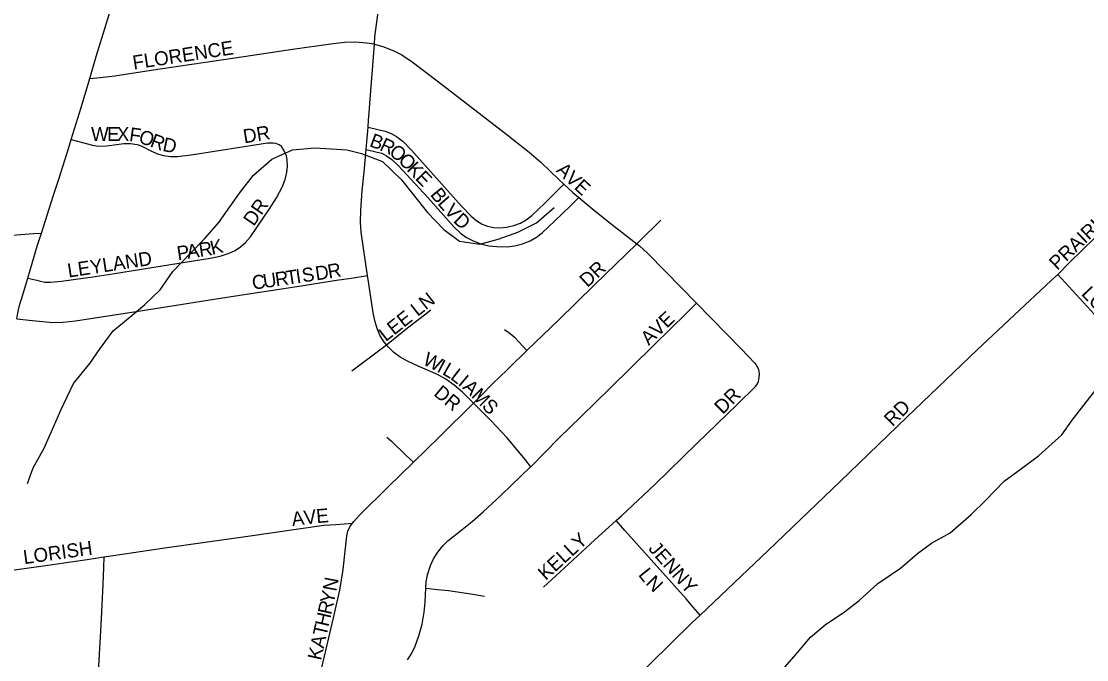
# Model space of a CAD drawing. Extents: x 1442749 to 1756758, y 235267 to 677782.
# Drawn here: x 1594493 to 1598304, y 531991 to 534274 of the extents above; entities that cross this region are included whole.
import ezdxf

# ---------------------------------------------------------------- set-up
doc = ezdxf.new("R2010")
doc.units = 0
for name, color, linetype in [('GM_X_City_Street', 7, 'Continuous'), ('GM_X_City_Street_Text', 7, 'Continuous'), ('GM_X_Minor_River', 7, 'Continuous'), ('GM_X_State_Route', 7, 'Continuous')]:
    doc.layers.add(name, color=color, linetype=linetype)

msp = doc.modelspace()

# ---------------------------------------------------------------- linework, layer by layer
at = {"layer": 'GM_X_City_Street'}
for points in [[(1595755.7, 534192.9), (1595757.6, 534218.5), (1595770, 534315.8), (1595780.6, 534376.9)], [(1594737.1, 534069.8), (1594774.5, 534073.6), (1594827, 534079), (1594956.8, 534099.6), (1595288, 534148.2), (1595463.2, 534174.5), (1595599.5, 534194.4), (1595648.1, 534199.8), (1595687, 534200.8), (1595729, 534197.9), (1595754.3, 534193.4), (1595755.7, 534192.9)], [(1595732.8, 533896.3), (1595734.8, 533921.3), (1595737.2, 533947.3), (1595740.8, 533996.3), (1595745.2, 534055.1), (1595755.7, 534192.9)], [(1595755.7, 534192.9), (1595785.3, 534184.1), (1595824.6, 534168.9), (1595853.2, 534154), (1595891.2, 534128.9), (1595985.4, 534058.1), (1596099.3, 533969.3), (1596224.2, 533873.2), (1596309.2, 533806.5), (1596351.4, 533770.3), (1596415, 533708.8), (1596433, 533692.4)], [(1595726.2, 533815.9), (1595726.3, 533816.6), (1595732.8, 533896.3)], [(1595732.8, 533896.3), (1595768.3, 533888), (1595793.9, 533882), (1595815.1, 533873.4), (1595835.1, 533862.1), (1595858.4, 533844), (1595888.4, 533813.8), (1595966.5, 533725), (1596067.8, 533613.2), (1596101.8, 533577.5), (1596122.1, 533560.9), (1596141.7, 533548.9), (1596160, 533541.9), (1596182.5, 533537.3), (1596205.4, 533535.9), (1596228.3, 533537.9), (1596253.9, 533543.7), (1596278.4, 533552.9), (1596298.6, 533563.9), (1596319.4, 533579.7), (1596364.4, 533622.9), (1596398.9, 533658), (1596433, 533692.4)], [(1594515.6, 533356.1), (1594547.6, 533348.2), (1594556.9, 533345.9), (1594576.9, 533341.8), (1594597, 533341.3), (1594636.6, 533344.9), (1594757, 533362.2), (1594818.6, 533371.8), (1595025.8, 533404.3), (1595168.4, 533426.8), (1595204.1, 533434.5), (1595235.7, 533444.9), (1595257.1, 533454.8), (1595276.9, 533467.8), (1595294.6, 533483.3), (1595312.2, 533503.7), (1595380.7, 533604.1), (1595405.9, 533642.8), (1595425.7, 533681.2), (1595436.6, 533709.2), (1595442.8, 533735.4), (1595444.5, 533755.7), (1595443.2, 533779.3), (1595440.6, 533793.3), (1595436.6, 533803.1), (1595431.8, 533813.2), (1595427.2, 533820.7), (1595421.6, 533828.9)], [(1594671, 533851.6), (1594706.2, 533842.2), (1594747.1, 533831.2), (1594769.1, 533828.4), (1594797.9, 533828.9), (1594859.8, 533837), (1594883.5, 533837), (1594907, 533833.3), (1594923.3, 533828.1), (1594956, 533811.5), (1594979.2, 533800.7), (1595000.6, 533794.3), (1595025.7, 533790.9), (1595051.3, 533791.4), (1595099.9, 533797.1), (1595372.8, 533839.4), (1595383.4, 533840.3), (1595393.2, 533840.3), (1595401.4, 533839), (1595407.9, 533836.8), (1595414.8, 533833.8), (1595421.6, 533828.9)], [(1595731.3, 533365.4), (1595708.6, 533520.5), (1595705.5, 533556), (1595706.6, 533598.2), (1595712.1, 533669.7), (1595719.5, 533734.9), (1595726.2, 533815.9)], [(1595726.2, 533815.9), (1595765.9, 533806.4), (1595781.8, 533802.6), (1595790.8, 533798.3), (1595799.4, 533793.8), (1595818, 533780.4), (1595841.5, 533757.7), (1595946.3, 533644.4), (1596040.1, 533539), (1596064.2, 533516.8), (1596085.4, 533501.4), (1596108.5, 533489), (1596136.1, 533478.6), (1596164.9, 533471.8), (1596194.2, 533468.6), (1596230.3, 533468.3), (1596256.3, 533471.6), (1596284.9, 533478.9), (1596312.5, 533489.5), (1596335.4, 533502.2), (1596356.3, 533518), (1596401.1, 533561.4), (1596455.4, 533613.8), (1596487.2, 533644.4)], [(1596433, 533692.4), (1596466, 533662.4), (1596487.2, 533644.4)], [(1596487.2, 533644.4), (1596543.8, 533596.5), (1596608.6, 533545.9), (1596694.2, 533478.5)], [(1596694.2, 533478.5), (1596705.5, 533489.5), (1596780.4, 533562.9)], [(1598200, 533369.2), (1598243.4, 533413.1), (1598332.2, 533499.3), (1598406.1, 533567.9)], [(1593624.3, 533445.5), (1593652.9, 533447.6), (1593778.5, 533456.7), (1593885.8, 533465.2), (1594098.2, 533482.8), (1594287.9, 533496.5), (1594421.9, 533507.3), (1594475.5, 533510.9), (1594536.2, 533515), (1594564.6, 533516.9)], [(1596300.8, 533096.9), (1596414.7, 533205.5), (1596542.8, 533332.3), (1596694.2, 533478.5)], [(1596694.2, 533478.5), (1596703.8, 533471), (1596733, 533445), (1596796.8, 533379.2), (1596908, 533266.1)], [(1594476.5, 533210.3), (1594520.7, 533206), (1594605.3, 533197.7), (1594640.9, 533198.6), (1594686.2, 533203.3), (1594926.3, 533240.4), (1595227.9, 533287.7), (1595477.7, 533326.3), (1595620.5, 533348.4), (1595672.4, 533356.4), (1595731.3, 533365.4)], [(1595798.4, 533117.6), (1595788.4, 533130.1), (1595775.4, 533152.1), (1595765.2, 533175.6), (1595757.9, 533200.2), (1595751.5, 533232.1), (1595735.7, 533335.6), (1595731.3, 533365.4)], [(1596921.4, 532151.1), (1597164.2, 532381.3), (1597422.3, 532628.6), (1597660.6, 532858.8), (1597911.5, 533099.3), (1598176.3, 533347)], [(1598176.3, 533347), (1598200, 533369.2)], [(1599088.7, 531687.2), (1599022.7, 531916.3), (1598945.1, 532194.3), (1598903.1, 532336.3), (1598885.5, 532387.6), (1598862.1, 532451.2), (1598838.1, 532508.4), (1598809.6, 532572.2), (1598785.9, 532619.7), (1598760.4, 532669.2), (1598730.8, 532721.2), (1598697, 532777.2), (1598654.3, 532843.1), (1598613.9, 532899.9), (1598588.6, 532935), (1598549.8, 532983.8), (1598449.9, 533097.6), (1598200, 533369.2)], [(1596314.9, 532681.5), (1596415.8, 532783.6), (1596494.8, 532861.7), (1596598, 532961.8), (1596754.7, 533116), (1596871.8, 533230.7), (1596908, 533266.1)], [(1596908, 533266.1), (1597068.2, 533103), (1597115.1, 533053.1), (1597120.9, 533045.4), (1597123, 533042.5), (1597127.3, 533035.4), (1597129.7, 533029.1), (1597131.1, 533021.6), (1597131.9, 533013.5), (1597132.2, 533008)], [(1595798.4, 533117.6), (1595835.8, 533147.6), (1595874.4, 533178.4), (1595934.4, 533224.5), (1595957.6, 533243)], [(1596221.2, 533172.2), (1596236.2, 533162), (1596247.3, 533153.2), (1596256.6, 533145.3), (1596300.8, 533096.9)], [(1595674.4, 533024.4), (1595798.4, 533117.6)], [(1596110.3, 532909), (1596070.7, 532947.6), (1596040.6, 532973.6), (1596010.7, 532994.7), (1595981.7, 533011.1), (1595912.2, 533041.3), (1595873.6, 533058.6), (1595848.4, 533072.9), (1595825.3, 533090.2), (1595804.4, 533110.2), (1595798.4, 533117.6)], [(1596110.3, 532909), (1596137.7, 532936.1), (1596179.6, 532978.6), (1596229.2, 533026.9), (1596240.4, 533038), (1596300.8, 533096.9)], [(1596619.9, 532488.6), (1596639.1, 532506.1), (1596759, 532617.9), (1596909.6, 532764.3), (1597053, 532904.1), (1597118.7, 532967.8), (1597123.5, 532973.8), (1597127, 532979.9), (1597129.5, 532986.4), (1597131.3, 532993.9), (1597132, 533001.4), (1597132.2, 533008)], [(1595895.4, 532697.6), (1595988.1, 532788.2), (1596110.3, 532909)], [(1596314.9, 532681.5), (1596294.6, 532707.2), (1596278.3, 532727.9), (1596229.6, 532785.8), (1596173.5, 532846), (1596122.4, 532897.1), (1596110.3, 532909)], [(1595799.7, 532787.3), (1595817.3, 532772.3), (1595869.8, 532722), (1595895.4, 532697.6)], [(1595677, 532479.2), (1595681.9, 532486.2), (1595702.1, 532508.5), (1595805.2, 532609.4), (1595895.4, 532697.6)], [(1595939.5, 532247.1), (1595940.8, 532269.4), (1595945.1, 532294.5), (1595956.4, 532328.2), (1595966.9, 532351.5), (1595982, 532376.1), (1595999.9, 532398.9), (1596018.2, 532416.7), (1596069.8, 532456.7), (1596105.5, 532485.8), (1596145.2, 532520.3), (1596210.2, 532580.8), (1596314.3, 532680.9), (1596314.9, 532681.5)], [(1594787.6, 532359.2), (1594870.5, 532371.6), (1594997.1, 532390.1), (1595302.4, 532432.9), (1595484.3, 532459), (1595575.2, 532472.2), (1595617.7, 532475.1), (1595677, 532479.2)], [(1595537.7, 531833), (1595552.2, 531898.2), (1595587.2, 532044.9), (1595609.4, 532140.7), (1595631.9, 532239.7), (1595644.4, 532313.6), (1595656.5, 532434.6), (1595660.8, 532451.3), (1595668.2, 532466.8), (1595677, 532479.2)], [(1596360.9, 532251.2), (1596404.4, 532290.9), (1596544.4, 532419.9), (1596619.9, 532488.6)], [(1596921.4, 532151.1), (1596896.5, 532179.6), (1596870.6, 532209.2), (1596787.2, 532302.2), (1596651.2, 532453.8), (1596619.9, 532488.6)], [(1594380, 532301.1), (1594546.1, 532323.2), (1594727.8, 532350.2), (1594787.6, 532359.2)], [(1594787.6, 532359.2), (1594786.4, 532320.7), (1594784.7, 532261.7), (1594777.8, 532137.3), (1594767.3, 531947.2), (1594765.5, 531913)], [(1595874.5, 531990.7), (1595888.8, 532012.6), (1595901.3, 532039.6), (1595914.9, 532077.3), (1595926.3, 532118.8), (1595933.9, 532161.2), (1595936.7, 532197.7), (1595939.5, 532247.1)], [(1595939.5, 532247.1), (1595981.7, 532242.9), (1596020.7, 532239), (1596100.9, 532227.1), (1596149.5, 532218.6)], [(1595961.2, 531253.1), (1596061.1, 531340.3), (1596221.8, 531486.5), (1596377.2, 531627.9), (1596452.5, 531697.2), (1596665.3, 531901.6), (1596892.9, 532124), (1596921.4, 532151.1)]]:
    msp.add_lwpolyline(points, dxfattribs=at)
at = {"layer": 'GM_X_Minor_River'}
for points in [[(1594514.6, 532621.8), (1594535.3, 532677.7), (1594574.2, 532747.5), (1594601, 532807.3), (1594634, 532883.2), (1594679.2, 532978.9), (1594738.2, 533050.4), (1594774.9, 533104.2), (1594821.7, 533167.8), (1594882.5, 533217.3), (1594933.1, 533260.8), (1594989.8, 533314.3), (1595034.7, 533380), (1595097.6, 533445.5), (1595148.3, 533497), (1595199.1, 533554.6), (1595237.9, 533610.4), (1595276.6, 533664.1), (1595323.4, 533723.7), (1595388.2, 533781.1), (1595462.8, 533814.4), (1595543, 533821.5), (1595601.1, 533818.8), (1595657.2, 533814.2), (1595709.1, 533801.5), (1595785, 533772.6), (1595852.3, 533707.6), (1595893.8, 533655), (1595945.1, 533590.2), (1596004.5, 533529.3), (1596060.2, 533488.6), (1596132.2, 533477.7), (1596198.6, 533495), (1596269, 533520.3), (1596335.5, 533553.6), (1596398.3, 533609.1)], [(1597198.2, 531935.1), (1597257.2, 532002.6), (1597316.1, 532072.1), (1597368.7, 532115.7), (1597437.5, 532163), (1597490, 532202.5), (1597556.9, 532263.9), (1597637.7, 532319.2), (1597698.5, 532370.6), (1597749, 532408.2), (1597815.6, 532445.5), (1597890.5, 532510.8), (1597941.2, 532560.4), (1598008.2, 532629.9), (1598070.9, 532675.3), (1598131.5, 532720.7), (1598214.6, 532796), (1598251.3, 532847.7), (1598294, 532901.4), (1598349, 532972.9)]]:
    msp.add_lwpolyline(points, dxfattribs=at)
at = {"layer": 'GM_X_State_Route'}
msp.add_lwpolyline([(1594476.5, 533210.3), (1594479.2, 533224.7), (1594482.8, 533242.8), (1594487.8, 533262.8), (1594493.3, 533281.3), (1594515.6, 533356.1), (1594549.8, 533470.6), (1594564.6, 533516.9), (1594607, 533649.2), (1594626.3, 533710.3), (1594662, 533822.9), (1594671, 533851.6), (1594706.9, 533966.6), (1594737.1, 534069.8), (1594760.3, 534149.1), (1594868.7, 534500.3), (1594877, 534526.5), (1594891.1, 534570.9)], dxfattribs=at)

# ---------------------------------------------------------------- texts
at = {"layer": 'GM_X_City_Street_Text'}
for s, rotation, p in [('FLORENCE', 8.6886, (1594894.7, 534101.7)), ('W', 359.8319, (1594741.9, 533846.6)), ('E', 359.7814, (1594799.1, 533846.4)), ('X', 359.8237, (1594834.3, 533846.3)), ('F', 351.6651, (1594876.5, 533846.3)), ('O', 341.0328, (1594908.9, 533841.7)), ('R', 339.4525, (1594950.2, 533827.6)), ('DR', 9.4564, (1595290.4, 533837.6)), ('B', 339.7679, (1595735.1, 533828.4)), ('D', 348.3022, (1594995.3, 533811.3)), ('R', 334.923, (1595771.2, 533815.1)), ('O', 322.1729, (1595804.6, 533799.9)), ('O', 314.4281, (1595838, 533774.1)), ('K', 313.8719, (1595868.8, 533742.7)), ('A', 316.8087, (1596402.9, 533738.3)), ('E', 313.9295, (1595899.3, 533711)), ('V', 316.8087, (1596435, 533708.2)), ('B', 308.8229, (1595953.1, 533654.2)), ('E', 317.3524, (1596467.4, 533677.7)), ('PRAIRIE AVE', 43.578, (1598198.1, 533381.9)), ('DR', 55.4949, (1595324, 533538.8)), ('L', 311.2265, (1595979.4, 533621.6)), ('V', 311.4592, (1596002.7, 533595)), ('D', 316.9487, (1596035.4, 533558.3)), ('R', 8.7757, (1595131.4, 533431.6)), ('K', 13.4988, (1595175, 533438.5)), ('LEYLAND', 8.61, (1594661.6, 533357.9)), ('P', 8.7752, (1595053.1, 533419.5)), ('A', 8.7761, (1595087.9, 533424.9)), ('R', 9.9384, (1595592.7, 533354.3)), ('DR', 42.8801, (1596517.7, 533320.3)), ('U', 8.4238, (1595360.6, 533319.9)), ('R', 8.4174, (1595404.1, 533326.3)), ('T', 8.447, (1595443.3, 533332.1)), ('I', 8.4206, (1595478.1, 533337.3)), ('S', 8.3881, (1595499.8, 533340.5)), ('D', 8.4799, (1595547.8, 533347.6)), ('C', 8.4323, (1595321.4, 533314.1)), ('LEE LN', 38.2846, (1595796.5, 533127.1)), ('LOWES', 313.3131, (1598282, 533298)), ('AVE', 43.664, (1596737.1, 533113.2)), ('W', 333.1342, (1595925.3, 533049.2)), ('I', 333.0637, (1595976.3, 533023.4)), ('L', 330.0247, (1595995.3, 533013.7)), ('L', 322.7913, (1596024.4, 532997.1)), ('I', 320.1385, (1596052, 532976.2)), ('DR', 320.2027, (1595964.7, 532938.9)), ('A', 316.3293, (1596068.2, 532962.7)), ('M', 315.1031, (1596099.8, 532932.5)), ('DR', 44.9844, (1597001.7, 532866.6)), ('S', 315.0193, (1596137.2, 532895.2)), ('RD', 45, (1597608.9, 532822.5)), ('E', 4.8136, (1595549.4, 532479.5)), ('A', 6.6588, (1595462.4, 532469.3)), ('V', 6.6865, (1595506.1, 532474.4)), ('KELLY', 42.3555, (1596368.4, 532272.8)), ('LORISH', 7.9654, (1594503.1, 532332.9)), ('JENNY', 311.3039, (1596733.4, 532387)), ('L', 308.455, (1596697.5, 532294.6)), ('N', 79.605, (1595619.6, 532233.6)), ('N', 314.468, (1596723.1, 532262.8)), ('Y', 77.5823, (1595609.7, 532188.7)), ('R', 77.3895, (1595601, 532149.9)), ('H', 77.3969, (1595591.4, 532107)), ('T', 77.3823, (1595583.8, 532072.6)), ('K', 77.3953, (1595564.6, 531986.8)), ('A', 77.3969, (1595574.2, 532029.7))]:
    msp.add_text(s, height=50, rotation=rotation, dxfattribs=at).set_placement(p)

doc.saveas('drawing.dxf')
